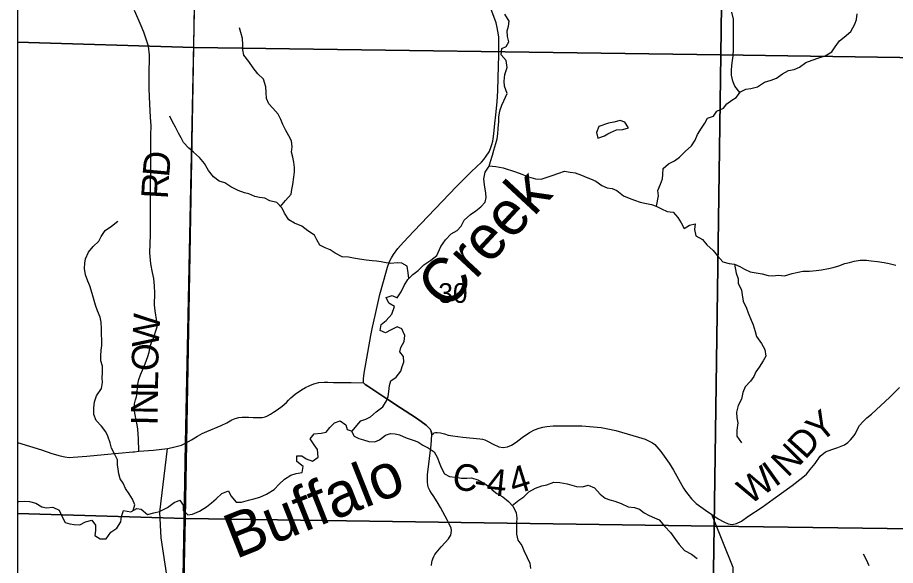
# Model space of a CAD drawing. Extents: x 0 to 191, y 0 to 55.
# Drawn here: x 143.275 to 144.211, y 21.314 to 21.897 of the extents above; entities that cross this region are included whole.
import ezdxf

# ---------------------------------------------------------------- set-up
doc = ezdxf.new("R2010")
doc.units = 0
for name, color, linetype in [('GM_X_Corporation', 7, 'Continuous'), ('GM_X_County_Road', 7, 'Continuous'), ('GM_X_County_Road_Text', 7, 'Continuous'), ('GM_X_Minor_Lake', 7, 'Continuous'), ('GM_X_Minor_River', 7, 'Continuous'), ('GM_X_Minor_River_Text', 7, 'Continuous'), ('GM_X_Section_Text', 7, 'Continuous'), ('GM_X_State_Route', 7, 'Continuous'), ('GM_X_Township_Road', 7, 'Continuous'), ('GM_X_Township_Road_Text', 7, 'Continuous')]:
    doc.layers.add(name, color=color, linetype=linetype)

msp = doc.modelspace()

# ---------------------------------------------------------------- linework, layer by layer
at = {"layer": 'GM_X_Corporation'}
for points in [[(143.27549, 22.87347), (143.27549, 18.61761), (147.4432, 18.61761)], [(145.17243, 20.8379), (145.0026, 20.83935), (144.83879, 20.8412), (144.83813, 20.84121), (144.68247, 20.843), (144.68103, 20.84301), (144.48078, 20.84928), (144.48001, 20.8493), (144.38601, 20.85042), (144.38393, 20.85044), (143.76753, 20.85776), (143.76581, 20.85778), (143.59684, 20.85979), (143.59377, 20.85978), (143.43969, 20.86008), (143.44633, 20.9725), (143.44634, 20.97335), (143.45423, 21.44428), (143.46697, 22.05758), (143.46706, 22.06228), (143.47318, 22.50936)]]:
    msp.add_lwpolyline(points, dxfattribs=at)
for points in [[(143.27549, 22.87347), (143.27549, 20.86338), (143.43969, 20.86008), (143.44633, 20.9725), (143.44634, 20.97335), (143.45423, 21.44428), (143.46697, 22.05758), (143.46706, 22.06228), (143.47318, 22.50936), (143.47319, 22.50998), (143.47629, 22.57462), (143.4763, 22.57542), (143.47809, 22.86847), (143.3138, 22.87294)], [(143.27549, 22.37115), (143.27549, 21.87142), (143.46331, 21.8654), (143.47107, 22.36785)], [(143.47107, 22.36785), (144.03127, 22.35852), (144.02463, 21.85779), (143.46331, 21.8654)], [(144.53007, 22.3498), (144.52512, 21.85042), (144.02463, 21.85779), (144.03127, 22.35852)], [(143.27549, 21.87142), (143.27549, 21.36927), (143.45444, 21.36394), (143.46331, 21.8654)], [(143.46331, 21.8654), (144.02463, 21.85779), (144.01747, 21.3556), (143.45444, 21.36394)], [(144.02463, 21.85779), (144.52512, 21.85042), (144.51719, 21.34898), (144.01747, 21.3556)], [(143.27549, 21.36927), (143.27549, 20.86557), (143.44367, 20.86246), (143.45444, 21.36394)], [(144.01747, 21.3556), (144.00991, 20.85435), (143.95611, 20.85372), (143.44367, 20.86246), (143.45444, 21.36394)], [(144.51719, 21.34898), (144.50909, 20.84639), (144.46967, 20.84688), (144.00991, 20.85435), (144.01747, 21.3556)]]:
    msp.add_lwpolyline(points, close=True, dxfattribs=at)
at = {"layer": 'GM_X_County_Road'}
for points in [[(143.40002, 21.43509), (143.40478, 21.43551), (143.42015, 21.43686), (143.43525, 21.43848), (143.44015, 21.43951), (143.44568, 21.44084), (143.44997, 21.44204), (143.45433, 21.44401), (143.46091, 21.44782), (143.46704, 21.45152), (143.47219, 21.4543), (143.47718, 21.4566), (143.49247, 21.46308), (143.49826, 21.46599), (143.50385, 21.46902), (143.50739, 21.4706), (143.51115, 21.47152), (143.51475, 21.4719), (143.51835, 21.47187), (143.52139, 21.47171), (143.52647, 21.47136), (143.53118, 21.47146), (143.53349, 21.47146), (143.53589, 21.47158), (143.53911, 21.47234), (143.5418, 21.47345), (143.54493, 21.47518), (143.54805, 21.47708), (143.55216, 21.47954), (143.55741, 21.48362), (143.56186, 21.48751), (143.56395, 21.48994), (143.56648, 21.49263), (143.57115, 21.49645), (143.57779, 21.5009), (143.58209, 21.50346), (143.5867, 21.50564), (143.59106, 21.50729), (143.59621, 21.50871), (143.60209, 21.50925), (143.60591, 21.50909), (143.61201, 21.50893), (143.6309, 21.50887), (143.64393, 21.50854)], [(143.64393, 21.50854), (143.64588, 21.50671), (143.64846, 21.50483), (143.65278, 21.50192), (143.66975, 21.49081), (143.68345, 21.4817), (143.69919, 21.47157), (143.70533, 21.46726), (143.71056, 21.46346), (143.71479, 21.45923), (143.71589, 21.4571), (143.71643, 21.45532), (143.71687, 21.45303)], [(143.71687, 21.45303), (143.718, 21.4541), (143.7194, 21.45513), (143.72077, 21.45556), (143.72242, 21.45561), (143.72595, 21.45502), (143.73007, 21.45405), (143.73401, 21.45275), (143.73672, 21.45223), (143.73928, 21.45186), (143.74987, 21.45064), (143.76793, 21.4487), (143.77057, 21.44837), (143.77336, 21.44766), (143.77607, 21.44647), (143.78209, 21.44324), (143.78811, 21.44031), (143.79271, 21.43968), (143.79717, 21.44027), (143.80152, 21.44202), (143.80639, 21.4454), (143.81311, 21.45004), (143.8208, 21.4555), (143.82593, 21.45825), (143.83098, 21.46007), (143.83488, 21.46111), (143.8392, 21.46193), (143.84607, 21.4626), (143.85146, 21.46264), (143.8603, 21.46279), (143.87657, 21.46249), (143.89701, 21.46089), (143.9041, 21.45955), (143.91272, 21.45755), (143.93688, 21.45064), (143.94397, 21.44837), (143.94769, 21.44674), (143.95163, 21.44458), (143.95434, 21.4428), (143.96077, 21.43533), (143.96953, 21.42288), (143.97407, 21.41541), (143.98469, 21.39639), (143.98689, 21.39297), (143.98934, 21.3897), (143.99331, 21.38483), (143.99829, 21.38008), (144.00312, 21.37625), (144.00825, 21.37283), (144.01497, 21.36819), (144.02183, 21.36365), (144.02777, 21.36022), (144.03248, 21.3582), (144.03659, 21.35753), (144.04136, 21.35845), (144.04651, 21.3612), (144.05343, 21.36598), (144.06844, 21.37603), (144.0802, 21.38436), (144.10053, 21.39906), (144.11198, 21.40788), (144.11572, 21.41124), (144.11976, 21.41602), (144.12491, 21.42257), (144.13054, 21.43029), (144.13605, 21.43501), (144.14285, 21.43734), (144.14928, 21.43954), (144.15621, 21.44242), (144.1597, 21.44481), (144.16258, 21.44769), (144.16643, 21.45234), (144.168, 21.4545), (144.17023, 21.45908), (144.17237, 21.46288), (144.1758, 21.46698), (144.18009, 21.47121), (144.18487, 21.47519), (144.20471, 21.49332), (144.21494, 21.5033)], [(143.27549, 21.44505), (143.30083, 21.43714), (143.3121, 21.43334), (143.32073, 21.43071), (143.32568, 21.4295), (143.33047, 21.42908), (143.33489, 21.42924), (143.34942, 21.43045), (143.36774, 21.43224), (143.39812, 21.43492), (143.40002, 21.43509)]]:
    msp.add_lwpolyline(points, dxfattribs=at)
at = {"layer": 'GM_X_Minor_Lake'}
for points in [[(143.90432, 21.77347), (143.90697, 21.77491), (143.91338, 21.77782), (143.92019, 21.77808), (143.92604, 21.77985), (143.92219, 21.78588), (143.91744, 21.78773), (143.91064, 21.78614), (143.90498, 21.78494), (143.89478, 21.78161)], [(143.89478, 21.78161), (143.89201, 21.77514), (143.89359, 21.76909), (143.90057, 21.77143), (143.90432, 21.77347)]]:
    msp.add_lwpolyline(points, dxfattribs=at)
at = {"layer": 'GM_X_Minor_River'}
for points in [[(143.78827, 21.79151), (143.78916, 21.79797), (143.79118, 21.80406), (143.79359, 21.80882), (143.79692, 21.81644), (143.79419, 21.82438), (143.79375, 21.82987), (143.79444, 21.8367), (143.79701, 21.84412), (143.79599, 21.8517), (143.79063, 21.85771), (143.79113, 21.86435), (143.79603, 21.86649), (143.79863, 21.87144), (143.79724, 21.87731), (143.79699, 21.88318), (143.79846, 21.88813), (143.79897, 21.89363), (143.79435, 21.90098)], [(143.9559, 21.69672), (143.95802, 21.70775), (143.95759, 21.71325), (143.96017, 21.7201), (143.96239, 21.72562), (143.96271, 21.73037), (143.96322, 21.73663), (143.96866, 21.7418), (143.97506, 21.74472), (143.9807, 21.74894), (143.9867, 21.75469), (143.99326, 21.76102), (143.99718, 21.76675), (143.99958, 21.77284), (144.00406, 21.77952), (144.00741, 21.78487), (144.01039, 21.79021), (144.01661, 21.79255), (144.02035, 21.79771), (144.02732, 21.80081), (144.03087, 21.80559), (144.03613, 21.80963), (144.04102, 21.81233), (144.04551, 21.81845), (144.05116, 21.82116), (144.05645, 21.82179), (144.06344, 21.82375), (144.07097, 21.82857), (144.07833, 21.83093), (144.08398, 21.83307), (144.09037, 21.83769), (144.09678, 21.84098), (144.10264, 21.84218), (144.10848, 21.8447), (144.11525, 21.84952), (144.12185, 21.85224), (144.12902, 21.8544), (144.13582, 21.85675), (144.14278, 21.8608), (144.14651, 21.86615), (144.1508, 21.87264), (144.15587, 21.87668), (144.16301, 21.88244), (144.16728, 21.89045), (144.16894, 21.8954), (144.16963, 21.90128)], [(144.04488, 21.8176), (144.03939, 21.82445), (144.03725, 21.82955), (144.03605, 21.83617), (144.03581, 21.84091), (144.03632, 21.84641), (144.03702, 21.85173), (144.03773, 21.85686), (144.03804, 21.86349), (144.03817, 21.86956), (144.03809, 21.87677), (144.0382, 21.88492), (144.03815, 21.88985), (144.0379, 21.89592), (144.03631, 21.90329)], [(143.55559, 21.69625), (143.56085, 21.70274), (143.56684, 21.70925), (143.56773, 21.71437), (143.56882, 21.71951), (143.56987, 21.72748), (143.57038, 21.73298), (143.57052, 21.73772), (143.56971, 21.7434), (143.5687, 21.74889), (143.56714, 21.754), (143.56784, 21.75969), (143.5672, 21.76613), (143.56431, 21.7716), (143.56083, 21.77782), (143.55794, 21.78348), (143.55599, 21.78896), (143.5529, 21.79443), (143.54735, 21.80082), (143.54313, 21.8057), (143.54062, 21.81118), (143.54017, 21.81762), (143.53992, 21.82368), (143.53737, 21.832), (143.53145, 21.83763), (143.52646, 21.84383), (143.52166, 21.85061), (143.51647, 21.85757), (143.51547, 21.86306), (143.51541, 21.86856), (143.51497, 21.875), (143.51339, 21.88143), (143.51201, 21.88654)], [(143.69215, 21.61951), (143.6917, 21.62576), (143.69031, 21.63277), (143.68478, 21.63593), (143.67986, 21.63626), (143.67324, 21.63562), (143.66793, 21.63614), (143.66281, 21.63742), (143.65788, 21.63812), (143.65314, 21.63826), (143.6467, 21.63896), (143.63987, 21.64003), (143.63323, 21.64129), (143.62792, 21.64218), (143.6211, 21.64268), (143.61386, 21.64659), (143.60853, 21.64994), (143.60301, 21.65235), (143.5975, 21.65495), (143.59441, 21.66061), (143.59171, 21.6657), (143.58484, 21.67037), (143.57817, 21.67523), (143.57056, 21.67838), (143.56447, 21.68192), (143.55966, 21.68927), (143.55733, 21.69436), (143.55178, 21.70037), (143.54419, 21.70219), (143.53886, 21.70498), (143.53317, 21.70568), (143.52824, 21.70696), (143.52196, 21.70955), (143.51722, 21.71083), (143.51056, 21.71342), (143.50276, 21.71713), (143.49628, 21.72142), (143.49039, 21.72326), (143.48429, 21.72794), (143.47892, 21.73471), (143.47449, 21.74187), (143.46931, 21.74826), (143.463, 21.75408), (143.45785, 21.7582), (143.45211, 21.7644), (143.44979, 21.7693), (143.44689, 21.77439), (143.44361, 21.78062), (143.44052, 21.78646), (143.43762, 21.7925)], [(143.48704, 21.38478), (143.49304, 21.39053), (143.50021, 21.39326), (143.50253, 21.38816), (143.50828, 21.38121), (143.51415, 21.38146), (143.52132, 21.38342), (143.52717, 21.385), (143.5336, 21.38658), (143.54076, 21.38988), (143.54866, 21.3947), (143.55409, 21.40063), (143.55991, 21.40581), (143.56649, 21.41024), (143.57234, 21.412), (143.57858, 21.41302), (143.57965, 21.41928), (143.57296, 21.42471), (143.57309, 21.43059), (143.5782, 21.43083), (143.58297, 21.42747), (143.58962, 21.42488), (143.59564, 21.42931), (143.5948, 21.43745), (143.59134, 21.44253), (143.5873, 21.44875), (143.59141, 21.4541), (143.59897, 21.45494), (143.60426, 21.45594), (143.608, 21.46072), (143.61306, 21.46589), (143.6191, 21.46803), (143.6252, 21.46374), (143.62658, 21.45882), (143.63171, 21.45679), (143.63676, 21.46309), (143.64106, 21.46807), (143.64634, 21.46983), (143.65143, 21.47215), (143.65743, 21.47771), (143.66439, 21.48271), (143.66849, 21.4892), (143.67033, 21.49396), (143.67103, 21.49928), (143.67154, 21.50573), (143.67319, 21.51049), (143.67883, 21.51434), (143.68388, 21.52083), (143.68515, 21.52578), (143.687, 21.53054), (143.68656, 21.53641), (143.68253, 21.5413), (143.68362, 21.54624), (143.68715, 21.55253), (143.68803, 21.55899), (143.68493, 21.56597), (143.67999, 21.5682), (143.67339, 21.5649), (143.66737, 21.56162), (143.66185, 21.56422), (143.66292, 21.57068), (143.66799, 21.57471), (143.67398, 21.5816), (143.67693, 21.58959), (143.67083, 21.59332), (143.66812, 21.59936), (143.67453, 21.60132), (143.67967, 21.59891), (143.68415, 21.60521), (143.6873, 21.61207), (143.69102, 21.61836), (143.69646, 21.62392), (143.70209, 21.62815), (143.70828, 21.63409), (143.71561, 21.6389), (143.72219, 21.64409), (143.72626, 21.65361), (143.7313, 21.66068), (143.73748, 21.667), (143.74369, 21.67066), (143.748, 21.67545), (143.75134, 21.68155), (143.75809, 21.68787), (143.76374, 21.69153), (143.76899, 21.69576), (143.77368, 21.70074), (143.77476, 21.70587), (143.77433, 21.7106), (143.77292, 21.71931), (143.7721, 21.72575), (143.77354, 21.73278), (143.77764, 21.73927), (143.77929, 21.74421), (143.78149, 21.75087), (143.78295, 21.75638), (143.78478, 21.76323), (143.78624, 21.76836), (143.78694, 21.77368), (143.78726, 21.77937), (143.78794, 21.78677), (143.78827, 21.79151)], [(143.77775, 21.73962), (143.78502, 21.73896), (143.7928, 21.73734), (143.80591, 21.73311), (143.81275, 21.73053), (143.8196, 21.72775), (143.82719, 21.72574), (143.83307, 21.72524), (143.83948, 21.72739), (143.84477, 21.72915), (143.85212, 21.73169), (143.85816, 21.73384), (143.86423, 21.73276), (143.86935, 21.73206), (143.876, 21.72947), (143.88114, 21.72763), (143.88589, 21.72578), (143.89159, 21.72337), (143.8977, 21.7187), (143.90359, 21.71629), (143.90891, 21.7154), (143.91366, 21.71317), (143.92091, 21.70756), (143.927, 21.70516), (143.93251, 21.70313), (143.93859, 21.70073), (143.94353, 21.69964), (143.95055, 21.6982), (143.95586, 21.69674), (143.96139, 21.69376), (143.96728, 21.69079), (143.97392, 21.6901), (143.97871, 21.68465), (143.98217, 21.679), (143.98546, 21.67277), (143.9911, 21.67624), (143.99733, 21.67783), (143.99664, 21.67156), (143.99803, 21.66494), (144.00489, 21.66122), (144.00968, 21.65539), (144.01637, 21.6494), (144.02116, 21.64376), (144.02672, 21.63737), (144.03356, 21.63535), (144.03905, 21.63484), (144.04495, 21.63225), (144.04971, 21.62946), (144.0558, 21.62649), (144.06206, 21.62541), (144.06851, 21.62453), (144.07496, 21.6229), (144.0797, 21.62238), (144.08594, 21.62301), (144.09239, 21.62251), (144.1005, 21.62487), (144.10693, 21.62626), (144.11203, 21.62726), (144.11884, 21.62753), (144.12622, 21.62798), (144.1319, 21.6288), (144.13908, 21.6302), (144.14418, 21.63139), (144.15022, 21.63316), (144.15663, 21.63551), (144.16155, 21.63651), (144.16664, 21.63808), (144.17307, 21.63909), (144.17989, 21.63898), (144.18463, 21.63846), (144.19145, 21.63758), (144.19847, 21.63652), (144.20397, 21.63544), (144.21099, 21.6338)], [(143.39879, 21.37242), (143.40039, 21.37841), (143.39786, 21.38464), (143.3944, 21.3901), (143.39055, 21.39594), (143.38804, 21.40141), (143.38477, 21.40631), (143.38339, 21.41142), (143.38258, 21.41634), (143.38197, 21.42126), (143.38191, 21.42657), (143.3792, 21.43204), (143.37554, 21.43883), (143.37396, 21.4445), (143.37162, 21.45149), (143.36949, 21.4564), (143.36488, 21.46242), (143.35914, 21.46824), (143.35662, 21.47466), (143.35673, 21.48187), (143.35761, 21.48832), (143.35963, 21.49441), (143.36504, 21.50224), (143.36611, 21.50889), (143.36569, 21.51362), (143.36601, 21.51912), (143.36593, 21.52633), (143.36417, 21.532), (143.36412, 21.53731), (143.36462, 21.54338), (143.36514, 21.54831), (143.36496, 21.56595), (143.36451, 21.57315), (143.36351, 21.57826), (143.36079, 21.58505), (143.35846, 21.5911), (143.3563, 21.59847), (143.35511, 21.60358), (143.35238, 21.6117), (143.35024, 21.6168), (143.3479, 21.6236), (143.34689, 21.63023), (143.34721, 21.63592), (143.34792, 21.64067), (143.35106, 21.64771), (143.35592, 21.65364), (143.36211, 21.65939), (143.36471, 21.66416), (143.36881, 21.67084), (143.37539, 21.67545), (143.38215, 21.68064)], [(144.03925, 21.63476), (144.04104, 21.62538), (144.04319, 21.61934), (144.04305, 21.61441), (144.04653, 21.60724), (144.04734, 21.60232), (144.04835, 21.5955), (144.05184, 21.58796), (144.0536, 21.58285), (144.0567, 21.57511), (144.05903, 21.57021), (144.06099, 21.56302), (144.06256, 21.55792), (144.06775, 21.55039), (144.07141, 21.54398), (144.07262, 21.53698), (144.06983, 21.53202), (144.06555, 21.52496), (144.06181, 21.52018), (144.05978, 21.51523), (144.05623, 21.51026), (144.05061, 21.50433), (144.04802, 21.49823), (144.04658, 21.49101), (144.04305, 21.48434), (144.04123, 21.47711), (144.04167, 21.47124), (144.04267, 21.46594), (144.04143, 21.45797), (144.04168, 21.45171), (144.04649, 21.44456)], [(143.631, 21.45706), (143.63385, 21.4515), (143.63898, 21.44928), (143.64411, 21.44762), (143.64962, 21.44597), (143.65606, 21.44566), (143.66115, 21.44761), (143.66754, 21.4526), (143.67282, 21.45455), (143.67756, 21.45403), (143.6823, 21.45294), (143.68953, 21.44979), (143.69694, 21.4474), (143.70188, 21.44574), (143.70703, 21.44201), (143.71273, 21.43922), (143.71921, 21.43512), (143.72288, 21.42871), (143.72464, 21.42342), (143.72658, 21.41813), (143.73006, 21.41153), (143.73558, 21.40855), (143.74164, 21.40804), (143.74828, 21.40697), (143.75396, 21.40703), (143.75888, 21.40727), (143.76591, 21.40507), (143.77124, 21.40228), (143.77601, 21.3991), (143.78116, 21.3946), (143.78613, 21.39048), (143.79241, 21.38695), (143.79833, 21.38189), (143.8035, 21.37663), (143.8066, 21.36984), (143.80723, 21.36416), (143.80709, 21.35922), (143.80678, 21.35221), (143.80702, 21.34709), (143.80822, 21.34085), (143.81244, 21.3352), (143.81458, 21.32991), (143.81825, 21.32256), (143.82097, 21.31652), (143.82197, 21.31084)], [(143.80225, 21.3779), (143.80949, 21.38352), (143.81456, 21.38717), (143.82019, 21.39235), (143.82715, 21.3964), (143.83376, 21.39856), (143.83924, 21.39994), (143.84659, 21.40248), (143.85303, 21.40236), (143.861, 21.40073), (143.86575, 21.39945), (143.87068, 21.39818), (143.87732, 21.39768), (143.88336, 21.39945), (143.89001, 21.39648), (143.89595, 21.38972), (143.90149, 21.3856), (143.90643, 21.38376), (143.91174, 21.3823), (143.91858, 21.38009), (143.92601, 21.37638), (143.93245, 21.37568), (143.93796, 21.37403), (143.94292, 21.3701), (143.94807, 21.36712), (143.95377, 21.36453), (143.95872, 21.36249), (143.96503, 21.35554), (143.97097, 21.34897), (143.97616, 21.34144), (143.98019, 21.33636), (143.98594, 21.32978), (143.99317, 21.32607), (143.99928, 21.3212)], [(143.27549, 21.38222), (143.27691, 21.38209), (143.28334, 21.38234), (143.28808, 21.3822), (143.29491, 21.38018), (143.30139, 21.37627), (143.30633, 21.37518), (143.31294, 21.376), (143.31979, 21.37285), (143.3227, 21.36643), (143.32617, 21.35983), (143.33111, 21.35817), (143.33585, 21.35746), (143.34173, 21.35715), (143.34775, 21.36043), (143.35455, 21.36201), (143.35858, 21.35675), (143.35845, 21.35106), (143.35794, 21.34574), (143.36346, 21.3422), (143.3699, 21.34245), (143.37475, 21.34933), (143.38133, 21.35375), (143.38562, 21.36024), (143.38632, 21.36594), (143.38833, 21.37241), (143.39611, 21.37097), (143.40251, 21.37445), (143.40725, 21.37374), (143.41375, 21.36811), (143.42073, 21.36989), (143.42678, 21.37128), (143.43526, 21.37554), (143.4422, 21.38111), (143.44843, 21.38344), (143.45189, 21.37798), (143.45176, 21.37248), (143.45673, 21.36779), (143.46183, 21.36841), (143.46937, 21.37171), (143.47671, 21.37634), (143.48216, 21.38075), (143.48704, 21.38478)], [(144.18246, 21.31344), (144.17974, 21.31986), (144.17646, 21.32608)]]:
    msp.add_lwpolyline(points, dxfattribs=at)
at = {"layer": 'GM_X_State_Route'}
for points in [[(143.64393, 21.50854), (143.64393, 21.51271), (143.64476, 21.51869), (143.64866, 21.54072), (143.65192, 21.55887), (143.65359, 21.56783), (143.65623, 21.58), (143.66152, 21.60252), (143.6652, 21.6165), (143.66958, 21.63151), (143.6718, 21.63756), (143.67389, 21.64159), (143.67604, 21.64521), (143.68056, 21.65146), (143.68668, 21.65814), (143.69759, 21.66981), (143.74312, 21.71765), (143.75884, 21.73342), (143.76947, 21.74343), (143.77211, 21.74635), (143.77469, 21.7499), (143.77768, 21.75441), (143.7792, 21.75803), (143.78066, 21.76241), (143.78171, 21.76588), (143.7824, 21.77068), (143.78317, 21.77721), (143.78393, 21.78472), (143.78484, 21.79383), (143.78623, 21.80787), (143.78699, 21.81934), (143.78741, 21.83338), (143.78796, 21.85764), (143.78817, 21.8671), (143.78796, 21.87676), (143.78713, 21.88288), (143.78643, 21.88705), (143.78518, 21.89178), (143.77969, 21.90728)], [(143.71687, 21.45303), (143.71643, 21.45532), (143.71589, 21.4571), (143.71479, 21.45923), (143.71056, 21.46346), (143.70533, 21.46726), (143.69919, 21.47157), (143.68345, 21.4817), (143.66975, 21.49081), (143.65278, 21.50192), (143.64846, 21.50483), (143.64588, 21.50671), (143.64393, 21.50854)], [(143.71643, 21.31385), (143.71681, 21.31746), (143.71711, 21.319), (143.71767, 21.32086), (143.71872, 21.32331), (143.71999, 21.32547), (143.72139, 21.32752), (143.72304, 21.32948), (143.72684, 21.33371), (143.7311, 21.33838), (143.73446, 21.34239), (143.73573, 21.34409), (143.73681, 21.34603), (143.73748, 21.34859), (143.73754, 21.35121), (143.73727, 21.35368), (143.7353, 21.3581), (143.73333, 21.36188), (143.72589, 21.37557), (143.72228, 21.38174), (143.71805, 21.38837), (143.71635, 21.39096), (143.71455, 21.3939), (143.71317, 21.39678), (143.71239, 21.39953), (143.71196, 21.40306), (143.71218, 21.41047), (143.71422, 21.42802), (143.71592, 21.44225), (143.71687, 21.45303)]]:
    msp.add_lwpolyline(points, dxfattribs=at)
at = {"layer": 'GM_X_Township_Road'}
for points in [[(143.41567, 21.83526), (143.41603, 21.85773), (143.41502, 21.86684), (143.4101, 21.88176), (143.40719, 21.88849), (143.40406, 21.89622), (143.39999, 21.90484)], [(143.40478, 21.43551), (143.40431, 21.44872), (143.40368, 21.45895), (143.40292, 21.4638), (143.4019, 21.46853), (143.40073, 21.47449), (143.39997, 21.47819), (143.39976, 21.4818), (143.40021, 21.48614), (143.40118, 21.49026), (143.40211, 21.49339), (143.40271, 21.49698), (143.40328, 21.50504), (143.40389, 21.50878), (143.40464, 21.51191), (143.40651, 21.51693), (143.4115, 21.52858), (143.41439, 21.53641), (143.4156, 21.54117), (143.41674, 21.54704), (143.4181, 21.55137), (143.4205, 21.55718), (143.42324, 21.56477), (143.42403, 21.56823), (143.42412, 21.57082), (143.42388, 21.57359), (143.42198, 21.58509), (143.42144, 21.59147), (143.42153, 21.60382), (143.42126, 21.61182), (143.42065, 21.61947), (143.4193, 21.626), (143.41749, 21.63524), (143.41638, 21.64701), (143.41698, 21.66595), (143.41701, 21.68458), (143.41722, 21.70599), (143.41703, 21.71737), (143.4173, 21.73605), (143.41743, 21.75403), (143.41759, 21.76514), (143.41746, 21.77226), (143.41762, 21.78214), (143.41717, 21.79132), (143.41635, 21.80527), (143.41582, 21.82152), (143.4156, 21.83126), (143.41567, 21.83526)], [(143.30053, 21.00214), (143.32273, 21.05164), (143.35004, 21.09943), (143.38589, 21.14892), (143.41833, 21.19501), (143.4354, 21.25474), (143.43711, 21.28717), (143.42858, 21.3435), (143.42687, 21.3708), (143.43525, 21.43848)], [(144.12072, 21.05585), (144.11648, 21.06042), (144.09449, 21.11207), (144.07866, 21.14205), (144.05179, 21.19298), (144.04731, 21.21398), (144.03942, 21.25096), (144.03765, 21.31185), (144.01497, 21.36819)]]:
    msp.add_lwpolyline(points, dxfattribs=at)

# ---------------------------------------------------------------- texts
at = {"layer": 'GM_X_County_Road_Text'}
for s, rotation, p in [('Y', 39.53878, (144.13025, 21.44364)), ('D', 48.1175, (144.11437, 21.4258)), ('N', 45.13883, (144.09564, 21.40693)), ('C', 348.67782, (143.73681, 21.39646)), ('I', 35.41149, (144.08219, 21.39683)), ('4', 354.27008, (143.77416, 21.38936)), ('4', 17.40396, (143.80395, 21.38887)), ('W', 35.23567, (144.05523, 21.37778)), ('-', 349.75297, (143.76026, 21.39177))]:
    msp.add_text(s, height=0.02841, rotation=rotation, dxfattribs=at).set_placement(p)
at = {"layer": 'GM_X_Minor_River_Text'}
for s, height, rotation, p in [('Creek', 0.047346, 47.11716, (143.73194, 21.58433)), ('Buffalo', 0.047347, 21.61707, (143.5078, 21.32051))]:
    msp.add_text(s, height=height, rotation=rotation, dxfattribs=at).set_placement(p)
at = {"layer": 'GM_X_Section_Text'}
msp.add_text('30', height=0.020928, rotation=0.00001, dxfattribs=at).set_placement((143.72366, 21.59362))
at = {"layer": 'GM_X_Township_Road_Text'}
for s, rotation, p in [('D', 84.65913, (143.43678, 21.72673)), ('R', 86.59847, (143.43542, 21.7037)), ('W', 87.0855, (143.42577, 21.54554)), ('O', 89.02731, (143.42535, 21.5208)), ('L', 89.22513, (143.42506, 21.49958)), ('N', 89.22482, (143.42473, 21.47458)), ('I', 89.21934, (143.42457, 21.46291))]:
    msp.add_text(s, height=0.02841, rotation=rotation, dxfattribs=at).set_placement(p)

doc.saveas('drawing.dxf')
